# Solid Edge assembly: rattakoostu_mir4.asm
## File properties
Author: Türk
Template: Iso Assembly.asm
Last saved by: Türk
Revision: 8
Application: Solid Edge
Username: Türk
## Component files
Rehv.par
VlegR18.par
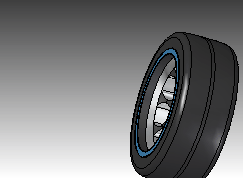
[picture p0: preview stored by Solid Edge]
